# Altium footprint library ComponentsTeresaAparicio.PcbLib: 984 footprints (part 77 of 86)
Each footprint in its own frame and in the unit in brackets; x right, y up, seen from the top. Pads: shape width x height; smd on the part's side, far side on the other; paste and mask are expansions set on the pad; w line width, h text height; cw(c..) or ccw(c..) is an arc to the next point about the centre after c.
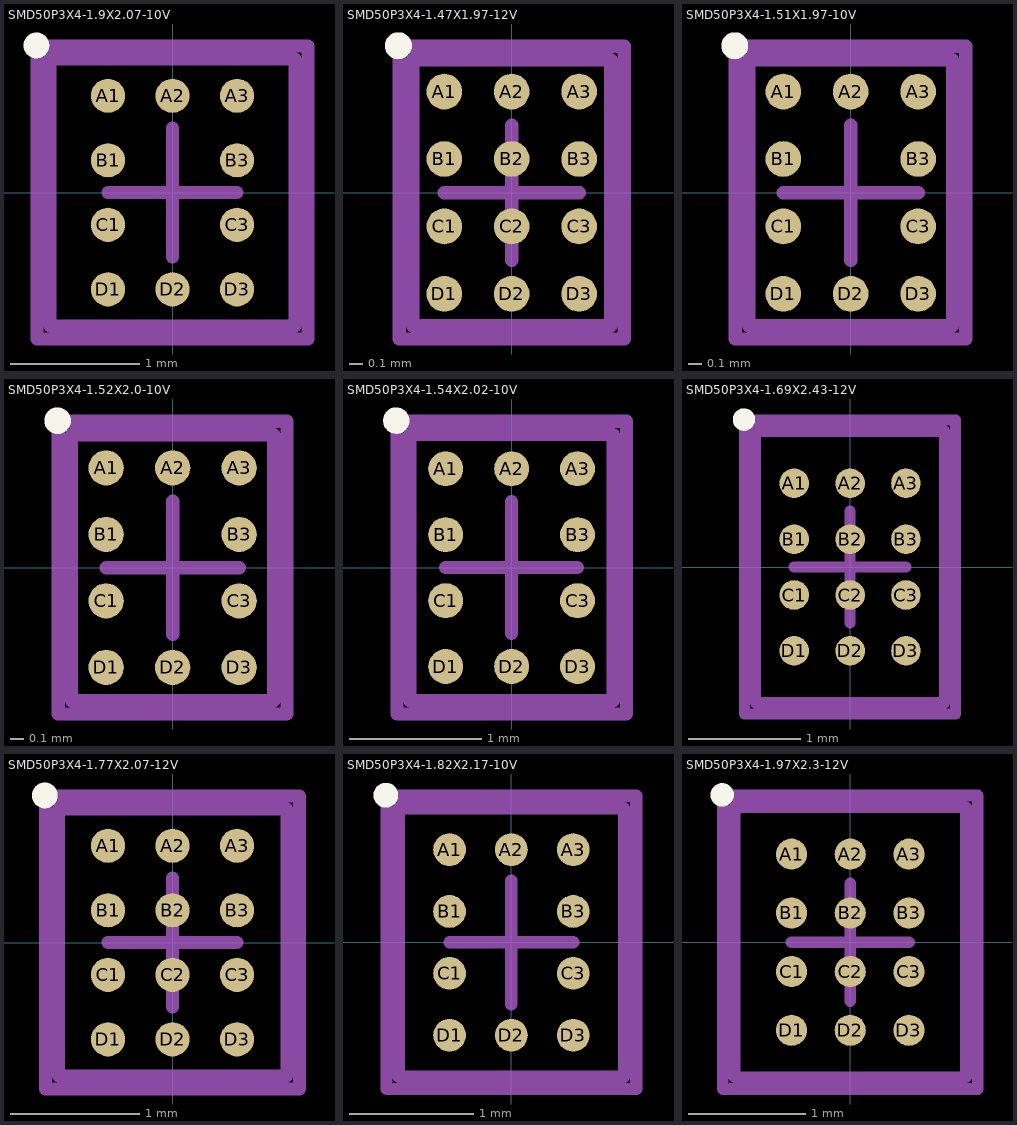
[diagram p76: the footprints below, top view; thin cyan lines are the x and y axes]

## SMD50P3X4-1.9X2.07-10V [mm] "Micro SMD, 10-Leads, Body 2.07x1.9mm, Pitch 0.5mm, NSC Recommended"
height 0.68
pads (10):
  round 0.265 smd paste-0.132 mask+0.05: A1(-0.5,0.75) A2(0,0.75) A3(0.5,0.75) B1(-0.5,0.25) B3(0.5,0.25) C1(-0.5,-0.25) C3(0.5,-0.25) D1(-0.5,-0.75) D2(0,-0.75) D3(0.5,-0.75)
Top Overlay:
  circle w0.1: c-1.055,1.14 r0.05
Top Paste:
  circle w0.05: c-0.6,0.7 r0.025
  circle w0.05: c-0.45,0.85 r0.025
  circle w0.05: c-0.45,0.7 r0.025
  circle w0.05: c-0.6,0.85 r0.025
  circle w0.05: c-0.075,0.7 r0.025
  circle w0.05: c0.075,0.85 r0.025
  circle w0.05: c0.075,0.7 r0.025
  circle w0.05: c-0.075,0.85 r0.025
  circle w0.05: c0.45,0.7 r0.025
  circle w0.05: c0.6,0.85 r0.025
  circle w0.05: c0.6,0.7 r0.025
  circle w0.05: c0.45,0.85 r0.025
  circle w0.05: c-0.6,0.175 r0.025
  circle w0.05: c-0.45,0.325 r0.025
  circle w0.05: c-0.45,0.175 r0.025
  circle w0.05: c-0.6,0.325 r0.025
  circle w0.05: c0.45,0.175 r0.025
  circle w0.05: c0.6,0.325 r0.025
  circle w0.05: c0.6,0.175 r0.025
  circle w0.05: c0.45,0.325 r0.025
  circle w0.05: c-0.6,-0.325 r0.025
  circle w0.05: c-0.45,-0.175 r0.025
  circle w0.05: c-0.45,-0.325 r0.025
  circle w0.05: c-0.6,-0.175 r0.025
  circle w0.05: c0.45,-0.325 r0.025
  circle w0.05: c0.6,-0.175 r0.025
  circle w0.05: c0.6,-0.325 r0.025
  circle w0.05: c0.45,-0.175 r0.025
  circle w0.05: c-0.6,-0.85 r0.025
  circle w0.05: c-0.45,-0.7 r0.025
  circle w0.05: c-0.45,-0.85 r0.025
  circle w0.05: c-0.6,-0.7 r0.025
  circle w0.05: c-0.075,-0.85 r0.025
  circle w0.05: c0.075,-0.7 r0.025
  circle w0.05: c0.075,-0.85 r0.025
  circle w0.05: c-0.075,-0.7 r0.025
  circle w0.05: c0.45,-0.85 r0.025
  circle w0.05: c0.6,-0.7 r0.025
  circle w0.05: c0.6,-0.85 r0.025
  circle w0.05: c0.45,-0.7 r0.025
  region: -0.6,0.85 -0.6,0.7 -0.45,0.7 -0.45,0.85
  region: -0.6,0.7 -0.6,0.85 -0.65,0.85 -0.65,0.7
  rectangle: -0.6,0.85 -0.45,0.9
  region: -0.45,0.85 -0.45,0.7 -0.4,0.7 -0.4,0.85
  region: -0.45,0.7 -0.6,0.7 -0.6,0.65 -0.45,0.65
  region: -0.075,0.85 -0.075,0.7 0.075,0.7 0.075,0.85
  region: -0.075,0.7 -0.075,0.85 -0.125,0.85 -0.125,0.7
  rectangle: -0.075,0.85 0.075,0.9
  region: 0.075,0.85 0.075,0.7 0.125,0.7 0.125,0.85
  region: 0.075,0.7 -0.075,0.7 -0.075,0.65 0.075,0.65
  region: 0.45,0.85 0.45,0.7 0.6,0.7 0.6,0.85
  region: 0.45,0.7 0.45,0.85 0.4,0.85 0.4,0.7
  rectangle: 0.45,0.85 0.6,0.9
  region: 0.6,0.85 0.6,0.7 0.65,0.7 0.65,0.85
  region: 0.6,0.7 0.45,0.7 0.45,0.65 0.6,0.65
  region: -0.6,0.325 -0.6,0.175 -0.45,0.175 -0.45,0.325
  region: -0.6,0.175 -0.6,0.325 -0.65,0.325 -0.65,0.175
  rectangle: -0.6,0.325 -0.45,0.375
  region: -0.45,0.325 -0.45,0.175 -0.4,0.175 -0.4,0.325
  region: -0.45,0.175 -0.6,0.175 -0.6,0.125 -0.45,0.125
  region: 0.45,0.325 0.45,0.175 0.6,0.175 0.6,0.325
  region: 0.45,0.175 0.45,0.325 0.4,0.325 0.4,0.175
  rectangle: 0.45,0.325 0.6,0.375
  region: 0.6,0.325 0.6,0.175 0.65,0.175 0.65,0.325
  region: 0.6,0.175 0.45,0.175 0.45,0.125 0.6,0.125
  region: -0.6,-0.175 -0.6,-0.325 -0.45,-0.325 -0.45,-0.175
  region: -0.6,-0.325 -0.6,-0.175 -0.65,-0.175 -0.65,-0.325
  rectangle: -0.6,-0.175 -0.45,-0.125
  region: -0.45,-0.175 -0.45,-0.325 -0.4,-0.325 -0.4,-0.175
  region: -0.45,-0.325 -0.6,-0.325 -0.6,-0.375 -0.45,-0.375
  region: 0.45,-0.175 0.45,-0.325 0.6,-0.325 0.6,-0.175
  region: 0.45,-0.325 0.45,-0.175 0.4,-0.175 0.4,-0.325
  rectangle: 0.45,-0.175 0.6,-0.125
  region: 0.6,-0.175 0.6,-0.325 0.65,-0.325 0.65,-0.175
  region: 0.6,-0.325 0.45,-0.325 0.45,-0.375 0.6,-0.375
  region: -0.6,-0.7 -0.6,-0.85 -0.45,-0.85 -0.45,-0.7
  region: -0.6,-0.85 -0.6,-0.7 -0.65,-0.7 -0.65,-0.85
  rectangle: -0.6,-0.7 -0.45,-0.65
  region: -0.45,-0.7 -0.45,-0.85 -0.4,-0.85 -0.4,-0.7
  region: -0.45,-0.85 -0.6,-0.85 -0.6,-0.9 -0.45,-0.9
  region: -0.075,-0.7 -0.075,-0.85 0.075,-0.85 0.075,-0.7
  region: -0.075,-0.85 -0.075,-0.7 -0.125,-0.7 -0.125,-0.85
  rectangle: -0.075,-0.7 0.075,-0.65
  region: 0.075,-0.7 0.075,-0.85 0.125,-0.85 0.125,-0.7
  region: 0.075,-0.85 -0.075,-0.85 -0.075,-0.9 0.075,-0.9
  region: 0.45,-0.7 0.45,-0.85 0.6,-0.85 0.6,-0.7
  region: 0.45,-0.85 0.45,-0.7 0.4,-0.7 0.4,-0.85
  rectangle: 0.45,-0.7 0.6,-0.65
  region: 0.6,-0.7 0.6,-0.85 0.65,-0.85 0.65,-0.7
  region: 0.6,-0.85 0.45,-0.85 0.45,-0.9 0.6,-0.9
Mechanical 13:
  lines w0.1: -0.95,-1.035 -0.95,1.035 0.95,1.035 0.95,-1.035 -0.95,-1.035
Mechanical 15:
  lines w0.1: -0.5,0 0.5,0 ; 0,-0.5 0,0.5 ; -1.05,-1.135 -1.05,1.135 1.05,1.135 1.05,-1.135 -1.05,-1.135
3D body: height 0.68, standoff 0, extent -0.95,-1.04 0.95,1.04

## SMD50P3X4-1.47X1.97-12V [mm] "Micro SMD, 12-Leads, Body 1.97x1.47mm, Pitch 0.5mm, NSC Recommended"
height 0.68
pads (12):
  round 0.265 smd paste-0.132 mask+0.05: A1(-0.5,0.75) A2(0,0.75) A3(0.5,0.75) B1(-0.5,0.25) B2(0,0.25) B3(0.5,0.25) C1(-0.5,-0.25) C2(0,-0.25) C3(0.5,-0.25) D1(-0.5,-0.75) D2(0,-0.75) D3(0.5,-0.75)
Top Overlay:
  circle w0.1: c-0.84,1.09 r0.05
Top Paste:
  circle w0.05: c-0.6,0.7 r0.025
  circle w0.05: c-0.45,0.85 r0.025
  circle w0.05: c-0.6,0.85 r0.025
  circle w0.05: c-0.45,0.7 r0.025
  circle w0.05: c0.45,0.85 r0.025
  circle w0.05: c0.6,0.7 r0.025
  circle w0.05: c0.6,0.85 r0.025
  circle w0.05: c0.45,0.7 r0.025
  circle w0.05: c0.6,-0.7 r0.025
  circle w0.05: c0.45,-0.85 r0.025
  circle w0.05: c0.6,-0.85 r0.025
  circle w0.05: c0.45,-0.7 r0.025
  circle w0.05: c-0.45,-0.85 r0.025
  circle w0.05: c-0.6,-0.7 r0.025
  circle w0.05: c-0.6,-0.85 r0.025
  circle w0.05: c-0.45,-0.7 r0.025
  circle w0.05: c-0.075,0.7 r0.025
  circle w0.05: c0.075,0.85 r0.025
  circle w0.05: c0.075,0.7 r0.025
  circle w0.05: c-0.075,0.85 r0.025
  circle w0.05: c-0.45,0.175 r0.025
  circle w0.05: c-0.6,0.325 r0.025
  circle w0.05: c-0.45,0.325 r0.025
  circle w0.05: c-0.6,0.175 r0.025
  circle w0.05: c-0.45,-0.325 r0.025
  circle w0.05: c-0.6,-0.175 r0.025
  circle w0.05: c-0.45,-0.175 r0.025
  circle w0.05: c-0.6,-0.325 r0.025
  circle w0.05: c0.075,-0.7 r0.025
  circle w0.05: c-0.075,-0.85 r0.025
  circle w0.05: c-0.075,-0.7 r0.025
  circle w0.05: c0.075,-0.85 r0.025
  circle w0.05: c0.45,-0.175 r0.025
  circle w0.05: c0.6,-0.325 r0.025
  circle w0.05: c0.45,-0.325 r0.025
  circle w0.05: c0.6,-0.175 r0.025
  circle w0.05: c0.45,0.325 r0.025
  circle w0.05: c0.6,0.175 r0.025
  circle w0.05: c0.45,0.175 r0.025
  circle w0.05: c0.6,0.325 r0.025
  circle w0.05: c0.075,0.175 r0.025
  circle w0.05: c-0.075,0.325 r0.025
  circle w0.05: c-0.075,0.175 r0.025
  circle w0.05: c0.075,0.325 r0.025
  circle w0.05: c0.075,-0.325 r0.025
  circle w0.05: c-0.075,-0.175 r0.025
  circle w0.05: c-0.075,-0.325 r0.025
  circle w0.05: c0.075,-0.175 r0.025
  region: -0.45,0.85 -0.45,0.7 -0.4,0.7 -0.4,0.85
  rectangle: -0.6,0.85 -0.45,0.9
  region: -0.6,0.7 -0.6,0.85 -0.65,0.85 -0.65,0.7
  region: -0.45,0.7 -0.6,0.7 -0.6,0.65 -0.45,0.65
  rectangle: -0.6,0.7 -0.45,0.85
  region: 0.6,0.7 0.45,0.7 0.45,0.65 0.6,0.65
  region: 0.6,0.85 0.6,0.7 0.65,0.7 0.65,0.85
  rectangle: 0.45,0.85 0.6,0.9
  region: 0.45,0.7 0.45,0.85 0.4,0.85 0.4,0.7
  region: 0.45,0.85 0.45,0.7 0.6,0.7 0.6,0.85
  region: 0.45,-0.85 0.45,-0.7 0.4,-0.7 0.4,-0.85
  region: 0.6,-0.85 0.45,-0.85 0.45,-0.9 0.6,-0.9
  region: 0.6,-0.7 0.6,-0.85 0.65,-0.85 0.65,-0.7
  rectangle: 0.45,-0.7 0.6,-0.65
  region: 0.6,-0.7 0.45,-0.7 0.45,-0.85 0.6,-0.85
  rectangle: -0.6,-0.7 -0.45,-0.65
  region: -0.6,-0.85 -0.6,-0.7 -0.65,-0.7 -0.65,-0.85
  region: -0.45,-0.85 -0.6,-0.85 -0.6,-0.9 -0.45,-0.9
  region: -0.45,-0.7 -0.45,-0.85 -0.4,-0.85 -0.4,-0.7
  region: -0.45,-0.85 -0.45,-0.7 -0.6,-0.7 -0.6,-0.85
  region: -0.075,0.85 -0.075,0.7 0.075,0.7 0.075,0.85
  region: -0.075,0.7 -0.075,0.85 -0.125,0.85 -0.125,0.7
  rectangle: -0.075,0.85 0.075,0.9
  region: 0.075,0.85 0.075,0.7 0.125,0.7 0.125,0.85
  region: 0.075,0.7 -0.075,0.7 -0.075,0.65 0.075,0.65
  rectangle: -0.6,0.175 -0.45,0.325
  region: -0.45,0.175 -0.6,0.175 -0.6,0.125 -0.45,0.125
  region: -0.6,0.175 -0.6,0.325 -0.65,0.325 -0.65,0.175
  rectangle: -0.6,0.325 -0.45,0.375
  region: -0.45,0.325 -0.45,0.175 -0.4,0.175 -0.4,0.325
  rectangle: -0.6,-0.325 -0.45,-0.175
  region: -0.45,-0.325 -0.6,-0.325 -0.6,-0.375 -0.45,-0.375
  region: -0.6,-0.325 -0.6,-0.175 -0.65,-0.175 -0.65,-0.325
  rectangle: -0.6,-0.175 -0.45,-0.125
  region: -0.45,-0.175 -0.45,-0.325 -0.4,-0.325 -0.4,-0.175
  region: 0.075,-0.85 0.075,-0.7 -0.075,-0.7 -0.075,-0.85
  region: 0.075,-0.7 0.075,-0.85 0.125,-0.85 0.125,-0.7
  region: 0.075,-0.85 -0.075,-0.85 -0.075,-0.9 0.075,-0.9
  region: -0.075,-0.85 -0.075,-0.7 -0.125,-0.7 -0.125,-0.85
  rectangle: -0.075,-0.7 0.075,-0.65
  region: 0.6,-0.175 0.45,-0.175 0.45,-0.325 0.6,-0.325
  rectangle: 0.45,-0.175 0.6,-0.125
  region: 0.6,-0.175 0.6,-0.325 0.65,-0.325 0.65,-0.175
  region: 0.6,-0.325 0.45,-0.325 0.45,-0.375 0.6,-0.375
  region: 0.45,-0.325 0.45,-0.175 0.4,-0.175 0.4,-0.325
  region: 0.6,0.325 0.45,0.325 0.45,0.175 0.6,0.175
  rectangle: 0.45,0.325 0.6,0.375
  region: 0.6,0.325 0.6,0.175 0.65,0.175 0.65,0.325
  region: 0.6,0.175 0.45,0.175 0.45,0.125 0.6,0.125
  region: 0.45,0.175 0.45,0.325 0.4,0.325 0.4,0.175
  region: -0.075,0.325 -0.075,0.175 0.075,0.175 0.075,0.325
  region: 0.125,0.175 0.125,0.325 0.075,0.325 0.075,0.175
  region: 0.075,0.375 -0.075,0.375 -0.075,0.325 0.075,0.325
  region: -0.125,0.325 -0.125,0.175 -0.075,0.175 -0.075,0.325
  rectangle: -0.075,0.125 0.075,0.175
  region: -0.075,-0.175 -0.075,-0.325 0.075,-0.325 0.075,-0.175
  region: 0.125,-0.325 0.125,-0.175 0.075,-0.175 0.075,-0.325
  region: 0.075,-0.125 -0.075,-0.125 -0.075,-0.175 0.075,-0.175
  region: -0.125,-0.175 -0.125,-0.325 -0.075,-0.325 -0.075,-0.175
  rectangle: -0.075,-0.375 0.075,-0.325
Mechanical 13:
  lines w0.1: -0.735,-0.985 0.735,-0.985 0.735,0.985 -0.735,0.985 -0.735,-0.985
Mechanical 15:
  lines w0.1: -0.5,0 0.5,0 ; 0,-0.5 0,0.5 ; -0.835,-1.085 0.835,-1.085 0.835,1.085 -0.835,1.085 -0.835,-1.085
3D body: height 0.68, standoff 0, extent -0.734,-0.984 0.734,0.984

## SMD50P3X4-1.51X1.97-10V [mm] "Micro SMD, 10-Leads, Body 1.97x1.51mm, Pitch 0.5mm, NSC Recommended"
height 0.68
pads (10):
  round 0.265 smd paste-0.132 mask+0.05: A1(-0.5,0.75) A2(0,0.75) A3(0.5,0.75) B1(-0.5,0.25) B3(0.5,0.25) C1(-0.5,-0.25) C3(0.5,-0.25) D1(-0.5,-0.75) D2(0,-0.75) D3(0.5,-0.75)
Top Overlay:
  circle w0.1: c-0.86,1.09 r0.05
Top Paste:
  circle w0.05: c0.45,-0.7 r0.025
  circle w0.05: c0.6,-0.85 r0.025
  circle w0.05: c0.6,-0.7 r0.025
  circle w0.05: c0.45,-0.85 r0.025
  circle w0.05: c-0.075,-0.7 r0.025
  circle w0.05: c0.075,-0.85 r0.025
  circle w0.05: c0.075,-0.7 r0.025
  circle w0.05: c-0.075,-0.85 r0.025
  circle w0.05: c-0.6,-0.7 r0.025
  circle w0.05: c-0.45,-0.85 r0.025
  circle w0.05: c-0.45,-0.7 r0.025
  circle w0.05: c-0.6,-0.85 r0.025
  circle w0.05: c0.45,-0.175 r0.025
  circle w0.05: c0.6,-0.325 r0.025
  circle w0.05: c0.6,-0.175 r0.025
  circle w0.05: c0.45,-0.325 r0.025
  circle w0.05: c-0.6,-0.175 r0.025
  circle w0.05: c-0.45,-0.325 r0.025
  circle w0.05: c-0.45,-0.175 r0.025
  circle w0.05: c-0.6,-0.325 r0.025
  circle w0.05: c0.45,0.325 r0.025
  circle w0.05: c0.6,0.175 r0.025
  circle w0.05: c0.6,0.325 r0.025
  circle w0.05: c0.45,0.175 r0.025
  circle w0.05: c-0.6,0.325 r0.025
  circle w0.05: c-0.45,0.175 r0.025
  circle w0.05: c-0.45,0.325 r0.025
  circle w0.05: c-0.6,0.175 r0.025
  circle w0.05: c0.45,0.85 r0.025
  circle w0.05: c0.6,0.7 r0.025
  circle w0.05: c0.6,0.85 r0.025
  circle w0.05: c0.45,0.7 r0.025
  circle w0.05: c-0.075,0.85 r0.025
  circle w0.05: c0.075,0.7 r0.025
  circle w0.05: c0.075,0.85 r0.025
  circle w0.05: c-0.075,0.7 r0.025
  circle w0.05: c-0.6,0.85 r0.025
  circle w0.05: c-0.45,0.7 r0.025
  circle w0.05: c-0.45,0.85 r0.025
  circle w0.05: c-0.6,0.7 r0.025
  region: 0.6,-0.85 0.45,-0.85 0.45,-0.9 0.6,-0.9
  region: 0.6,-0.7 0.6,-0.85 0.65,-0.85 0.65,-0.7
  rectangle: 0.45,-0.7 0.6,-0.65
  region: 0.45,-0.85 0.45,-0.7 0.4,-0.7 0.4,-0.85
  region: 0.45,-0.7 0.45,-0.85 0.6,-0.85 0.6,-0.7
  region: 0.075,-0.85 -0.075,-0.85 -0.075,-0.9 0.075,-0.9
  region: 0.075,-0.7 0.075,-0.85 0.125,-0.85 0.125,-0.7
  rectangle: -0.075,-0.7 0.075,-0.65
  region: -0.075,-0.85 -0.075,-0.7 -0.125,-0.7 -0.125,-0.85
  region: -0.075,-0.7 -0.075,-0.85 0.075,-0.85 0.075,-0.7
  region: -0.45,-0.85 -0.6,-0.85 -0.6,-0.9 -0.45,-0.9
  region: -0.45,-0.7 -0.45,-0.85 -0.4,-0.85 -0.4,-0.7
  rectangle: -0.6,-0.7 -0.45,-0.65
  region: -0.6,-0.85 -0.6,-0.7 -0.65,-0.7 -0.65,-0.85
  region: -0.6,-0.7 -0.6,-0.85 -0.45,-0.85 -0.45,-0.7
  region: 0.6,-0.325 0.45,-0.325 0.45,-0.375 0.6,-0.375
  region: 0.6,-0.175 0.6,-0.325 0.65,-0.325 0.65,-0.175
  rectangle: 0.45,-0.175 0.6,-0.125
  region: 0.45,-0.325 0.45,-0.175 0.4,-0.175 0.4,-0.325
  region: 0.45,-0.175 0.45,-0.325 0.6,-0.325 0.6,-0.175
  region: -0.45,-0.325 -0.6,-0.325 -0.6,-0.375 -0.45,-0.375
  region: -0.45,-0.175 -0.45,-0.325 -0.4,-0.325 -0.4,-0.175
  rectangle: -0.6,-0.175 -0.45,-0.125
  region: -0.6,-0.325 -0.6,-0.175 -0.65,-0.175 -0.65,-0.325
  region: -0.6,-0.175 -0.6,-0.325 -0.45,-0.325 -0.45,-0.175
  region: 0.6,0.175 0.45,0.175 0.45,0.125 0.6,0.125
  region: 0.6,0.325 0.6,0.175 0.65,0.175 0.65,0.325
  rectangle: 0.45,0.325 0.6,0.375
  region: 0.45,0.175 0.45,0.325 0.4,0.325 0.4,0.175
  region: 0.45,0.325 0.45,0.175 0.6,0.175 0.6,0.325
  region: -0.45,0.175 -0.6,0.175 -0.6,0.125 -0.45,0.125
  region: -0.45,0.325 -0.45,0.175 -0.4,0.175 -0.4,0.325
  rectangle: -0.6,0.325 -0.45,0.375
  region: -0.6,0.175 -0.6,0.325 -0.65,0.325 -0.65,0.175
  region: -0.6,0.325 -0.6,0.175 -0.45,0.175 -0.45,0.325
  region: 0.6,0.7 0.45,0.7 0.45,0.65 0.6,0.65
  region: 0.6,0.85 0.6,0.7 0.65,0.7 0.65,0.85
  rectangle: 0.45,0.85 0.6,0.9
  region: 0.45,0.7 0.45,0.85 0.4,0.85 0.4,0.7
  region: 0.45,0.85 0.45,0.7 0.6,0.7 0.6,0.85
  region: 0.075,0.7 -0.075,0.7 -0.075,0.65 0.075,0.65
  region: 0.075,0.85 0.075,0.7 0.125,0.7 0.125,0.85
  rectangle: -0.075,0.85 0.075,0.9
  region: -0.075,0.7 -0.075,0.85 -0.125,0.85 -0.125,0.7
  region: -0.075,0.85 -0.075,0.7 0.075,0.7 0.075,0.85
  region: -0.45,0.7 -0.6,0.7 -0.6,0.65 -0.45,0.65
  region: -0.45,0.85 -0.45,0.7 -0.4,0.7 -0.4,0.85
  rectangle: -0.6,0.85 -0.45,0.9
  region: -0.6,0.7 -0.6,0.85 -0.65,0.85 -0.65,0.7
  region: -0.6,0.85 -0.6,0.7 -0.45,0.7 -0.45,0.85
Mechanical 13:
  lines w0.1: -0.755,-0.985 0.755,-0.985 0.755,0.985 -0.755,0.985 -0.755,-0.985
Mechanical 15:
  lines w0.1: -0.5,0 0.5,0 ; 0,-0.5 0,0.5 ; -0.855,-1.085 0.855,-1.085 0.855,1.085 -0.855,1.085 -0.855,-1.085
3D body: height 0.68, standoff 0, extent -0.76,-0.985 0.76,0.985

## SMD50P3X4-1.52X2.0-10V [mm] "Micro SMD, 10-Leads, Body 2.0x1.52mm, Pitch 0.5mm, NSC Recommended"
height 1.05
pads (10):
  round 0.265 smd paste-0.132 mask+0.05: A1(-0.5,0.75) A2(0,0.75) A3(0.5,0.75) B1(-0.5,0.25) B3(0.5,0.25) C1(-0.5,-0.25) C3(0.5,-0.25) D1(-0.5,-0.75) D2(0,-0.75) D3(0.5,-0.75)
Top Overlay:
  circle w0.1: c-0.865,1.105 r0.05
Top Paste:
  circle w0.05: c-0.6,0.7 r0.025
  circle w0.05: c-0.45,0.85 r0.025
  circle w0.05: c-0.6,0.85 r0.025
  circle w0.05: c-0.45,0.7 r0.025
  circle w0.05: c0.45,0.85 r0.025
  circle w0.05: c0.6,0.7 r0.025
  circle w0.05: c0.6,0.85 r0.025
  circle w0.05: c0.45,0.7 r0.025
  circle w0.05: c0.6,-0.7 r0.025
  circle w0.05: c0.45,-0.85 r0.025
  circle w0.05: c0.6,-0.85 r0.025
  circle w0.05: c0.45,-0.7 r0.025
  circle w0.05: c-0.45,-0.85 r0.025
  circle w0.05: c-0.6,-0.7 r0.025
  circle w0.05: c-0.6,-0.85 r0.025
  circle w0.05: c-0.45,-0.7 r0.025
  circle w0.05: c-0.075,0.7 r0.025
  circle w0.05: c0.075,0.85 r0.025
  circle w0.05: c0.075,0.7 r0.025
  circle w0.05: c-0.075,0.85 r0.025
  circle w0.05: c-0.45,0.175 r0.025
  circle w0.05: c-0.6,0.325 r0.025
  circle w0.05: c-0.45,0.325 r0.025
  circle w0.05: c-0.6,0.175 r0.025
  circle w0.05: c-0.45,-0.325 r0.025
  circle w0.05: c-0.6,-0.175 r0.025
  circle w0.05: c-0.45,-0.175 r0.025
  circle w0.05: c-0.6,-0.325 r0.025
  circle w0.05: c0.075,-0.7 r0.025
  circle w0.05: c-0.075,-0.85 r0.025
  circle w0.05: c-0.075,-0.7 r0.025
  circle w0.05: c0.075,-0.85 r0.025
  circle w0.05: c0.45,-0.175 r0.025
  circle w0.05: c0.6,-0.325 r0.025
  circle w0.05: c0.45,-0.325 r0.025
  circle w0.05: c0.6,-0.175 r0.025
  circle w0.05: c0.45,0.325 r0.025
  circle w0.05: c0.6,0.175 r0.025
  circle w0.05: c0.45,0.175 r0.025
  circle w0.05: c0.6,0.325 r0.025
  region: -0.45,0.85 -0.45,0.7 -0.4,0.7 -0.4,0.85
  rectangle: -0.6,0.85 -0.45,0.9
  region: -0.6,0.7 -0.6,0.85 -0.65,0.85 -0.65,0.7
  region: -0.45,0.7 -0.6,0.7 -0.6,0.65 -0.45,0.65
  rectangle: -0.6,0.7 -0.45,0.85
  region: 0.6,0.7 0.45,0.7 0.45,0.65 0.6,0.65
  region: 0.6,0.85 0.6,0.7 0.65,0.7 0.65,0.85
  rectangle: 0.45,0.85 0.6,0.9
  region: 0.45,0.7 0.45,0.85 0.4,0.85 0.4,0.7
  region: 0.45,0.85 0.45,0.7 0.6,0.7 0.6,0.85
  region: 0.45,-0.85 0.45,-0.7 0.4,-0.7 0.4,-0.85
  region: 0.6,-0.85 0.45,-0.85 0.45,-0.9 0.6,-0.9
  region: 0.6,-0.7 0.6,-0.85 0.65,-0.85 0.65,-0.7
  rectangle: 0.45,-0.7 0.6,-0.65
  region: 0.6,-0.7 0.45,-0.7 0.45,-0.85 0.6,-0.85
  rectangle: -0.6,-0.7 -0.45,-0.65
  region: -0.6,-0.85 -0.6,-0.7 -0.65,-0.7 -0.65,-0.85
  region: -0.45,-0.85 -0.6,-0.85 -0.6,-0.9 -0.45,-0.9
  region: -0.45,-0.7 -0.45,-0.85 -0.4,-0.85 -0.4,-0.7
  region: -0.45,-0.85 -0.45,-0.7 -0.6,-0.7 -0.6,-0.85
  region: -0.075,0.85 -0.075,0.7 0.075,0.7 0.075,0.85
  region: -0.075,0.7 -0.075,0.85 -0.125,0.85 -0.125,0.7
  rectangle: -0.075,0.85 0.075,0.9
  region: 0.075,0.85 0.075,0.7 0.125,0.7 0.125,0.85
  region: 0.075,0.7 -0.075,0.7 -0.075,0.65 0.075,0.65
  rectangle: -0.6,0.175 -0.45,0.325
  region: -0.45,0.175 -0.6,0.175 -0.6,0.125 -0.45,0.125
  region: -0.6,0.175 -0.6,0.325 -0.65,0.325 -0.65,0.175
  rectangle: -0.6,0.325 -0.45,0.375
  region: -0.45,0.325 -0.45,0.175 -0.4,0.175 -0.4,0.325
  rectangle: -0.6,-0.325 -0.45,-0.175
  region: -0.45,-0.325 -0.6,-0.325 -0.6,-0.375 -0.45,-0.375
  region: -0.6,-0.325 -0.6,-0.175 -0.65,-0.175 -0.65,-0.325
  rectangle: -0.6,-0.175 -0.45,-0.125
  region: -0.45,-0.175 -0.45,-0.325 -0.4,-0.325 -0.4,-0.175
  region: 0.075,-0.85 0.075,-0.7 -0.075,-0.7 -0.075,-0.85
  region: 0.075,-0.7 0.075,-0.85 0.125,-0.85 0.125,-0.7
  region: 0.075,-0.85 -0.075,-0.85 -0.075,-0.9 0.075,-0.9
  region: -0.075,-0.85 -0.075,-0.7 -0.125,-0.7 -0.125,-0.85
  rectangle: -0.075,-0.7 0.075,-0.65
  region: 0.6,-0.175 0.45,-0.175 0.45,-0.325 0.6,-0.325
  rectangle: 0.45,-0.175 0.6,-0.125
  region: 0.6,-0.175 0.6,-0.325 0.65,-0.325 0.65,-0.175
  region: 0.6,-0.325 0.45,-0.325 0.45,-0.375 0.6,-0.375
  region: 0.45,-0.325 0.45,-0.175 0.4,-0.175 0.4,-0.325
  region: 0.6,0.325 0.45,0.325 0.45,0.175 0.6,0.175
  rectangle: 0.45,0.325 0.6,0.375
  region: 0.6,0.325 0.6,0.175 0.65,0.175 0.65,0.325
  region: 0.6,0.175 0.45,0.175 0.45,0.125 0.6,0.125
  region: 0.45,0.175 0.45,0.325 0.4,0.325 0.4,0.175
Mechanical 13:
  lines w0.1: -0.76,-1 -0.76,1 0.76,1 0.76,-1 -0.76,-1
Mechanical 15:
  lines w0.1: -0.5,0 0.5,0 ; 0,-0.5 0,0.5 ; -0.86,-1.1 -0.86,1.1 0.86,1.1 0.86,-1.1 -0.86,-1.1
3D body: height 1.05, standoff 0, extent -0.759,-0.999 0.759,0.999

## SMD50P3X4-1.54X2.02-10V [mm] "Micro SMD, 10-Leads, Body 2.02x1.54mm, Pitch 0.5mm, NSC Recommended"
height 0.68
pads (10):
  round 0.265 smd paste-0.132 mask+0.05: A1(-0.5,0.75) A2(0,0.75) A3(0.5,0.75) B1(-0.5,0.25) B3(0.5,0.25) C1(-0.5,-0.25) C3(0.5,-0.25) D1(-0.5,-0.75) D2(0,-0.75) D3(0.5,-0.75)
Top Overlay:
  circle w0.1: c-0.875,1.115 r0.05
Top Paste:
  circle w0.05: c-0.6,0.7 r0.025
  circle w0.05: c-0.45,0.85 r0.025
  circle w0.05: c-0.6,0.85 r0.025
  circle w0.05: c-0.45,0.7 r0.025
  circle w0.05: c0.45,0.85 r0.025
  circle w0.05: c0.6,0.7 r0.025
  circle w0.05: c0.6,0.85 r0.025
  circle w0.05: c0.45,0.7 r0.025
  circle w0.05: c0.6,-0.7 r0.025
  circle w0.05: c0.45,-0.85 r0.025
  circle w0.05: c0.6,-0.85 r0.025
  circle w0.05: c0.45,-0.7 r0.025
  circle w0.05: c-0.45,-0.85 r0.025
  circle w0.05: c-0.6,-0.7 r0.025
  circle w0.05: c-0.6,-0.85 r0.025
  circle w0.05: c-0.45,-0.7 r0.025
  circle w0.05: c-0.075,0.7 r0.025
  circle w0.05: c0.075,0.85 r0.025
  circle w0.05: c0.075,0.7 r0.025
  circle w0.05: c-0.075,0.85 r0.025
  circle w0.05: c-0.45,0.175 r0.025
  circle w0.05: c-0.6,0.325 r0.025
  circle w0.05: c-0.45,0.325 r0.025
  circle w0.05: c-0.6,0.175 r0.025
  circle w0.05: c-0.45,-0.325 r0.025
  circle w0.05: c-0.6,-0.175 r0.025
  circle w0.05: c-0.45,-0.175 r0.025
  circle w0.05: c-0.6,-0.325 r0.025
  circle w0.05: c0.075,-0.7 r0.025
  circle w0.05: c-0.075,-0.85 r0.025
  circle w0.05: c-0.075,-0.7 r0.025
  circle w0.05: c0.075,-0.85 r0.025
  circle w0.05: c0.45,-0.175 r0.025
  circle w0.05: c0.6,-0.325 r0.025
  circle w0.05: c0.45,-0.325 r0.025
  circle w0.05: c0.6,-0.175 r0.025
  circle w0.05: c0.45,0.325 r0.025
  circle w0.05: c0.6,0.175 r0.025
  circle w0.05: c0.45,0.175 r0.025
  circle w0.05: c0.6,0.325 r0.025
  region: -0.45,0.85 -0.45,0.7 -0.4,0.7 -0.4,0.85
  rectangle: -0.6,0.85 -0.45,0.9
  region: -0.6,0.7 -0.6,0.85 -0.65,0.85 -0.65,0.7
  region: -0.45,0.7 -0.6,0.7 -0.6,0.65 -0.45,0.65
  rectangle: -0.6,0.7 -0.45,0.85
  region: 0.6,0.7 0.45,0.7 0.45,0.65 0.6,0.65
  region: 0.6,0.85 0.6,0.7 0.65,0.7 0.65,0.85
  rectangle: 0.45,0.85 0.6,0.9
  region: 0.45,0.7 0.45,0.85 0.4,0.85 0.4,0.7
  region: 0.45,0.85 0.45,0.7 0.6,0.7 0.6,0.85
  region: 0.45,-0.85 0.45,-0.7 0.4,-0.7 0.4,-0.85
  region: 0.6,-0.85 0.45,-0.85 0.45,-0.9 0.6,-0.9
  region: 0.6,-0.7 0.6,-0.85 0.65,-0.85 0.65,-0.7
  rectangle: 0.45,-0.7 0.6,-0.65
  region: 0.6,-0.7 0.45,-0.7 0.45,-0.85 0.6,-0.85
  rectangle: -0.6,-0.7 -0.45,-0.65
  region: -0.6,-0.85 -0.6,-0.7 -0.65,-0.7 -0.65,-0.85
  region: -0.45,-0.85 -0.6,-0.85 -0.6,-0.9 -0.45,-0.9
  region: -0.45,-0.7 -0.45,-0.85 -0.4,-0.85 -0.4,-0.7
  region: -0.45,-0.85 -0.45,-0.7 -0.6,-0.7 -0.6,-0.85
  region: -0.075,0.85 -0.075,0.7 0.075,0.7 0.075,0.85
  region: -0.075,0.7 -0.075,0.85 -0.125,0.85 -0.125,0.7
  rectangle: -0.075,0.85 0.075,0.9
  region: 0.075,0.85 0.075,0.7 0.125,0.7 0.125,0.85
  region: 0.075,0.7 -0.075,0.7 -0.075,0.65 0.075,0.65
  rectangle: -0.6,0.175 -0.45,0.325
  region: -0.45,0.175 -0.6,0.175 -0.6,0.125 -0.45,0.125
  region: -0.6,0.175 -0.6,0.325 -0.65,0.325 -0.65,0.175
  rectangle: -0.6,0.325 -0.45,0.375
  region: -0.45,0.325 -0.45,0.175 -0.4,0.175 -0.4,0.325
  rectangle: -0.6,-0.325 -0.45,-0.175
  region: -0.45,-0.325 -0.6,-0.325 -0.6,-0.375 -0.45,-0.375
  region: -0.6,-0.325 -0.6,-0.175 -0.65,-0.175 -0.65,-0.325
  rectangle: -0.6,-0.175 -0.45,-0.125
  region: -0.45,-0.175 -0.45,-0.325 -0.4,-0.325 -0.4,-0.175
  region: 0.075,-0.85 0.075,-0.7 -0.075,-0.7 -0.075,-0.85
  region: 0.075,-0.7 0.075,-0.85 0.125,-0.85 0.125,-0.7
  region: 0.075,-0.85 -0.075,-0.85 -0.075,-0.9 0.075,-0.9
  region: -0.075,-0.85 -0.075,-0.7 -0.125,-0.7 -0.125,-0.85
  rectangle: -0.075,-0.7 0.075,-0.65
  region: 0.6,-0.175 0.45,-0.175 0.45,-0.325 0.6,-0.325
  rectangle: 0.45,-0.175 0.6,-0.125
  region: 0.6,-0.175 0.6,-0.325 0.65,-0.325 0.65,-0.175
  region: 0.6,-0.325 0.45,-0.325 0.45,-0.375 0.6,-0.375
  region: 0.45,-0.325 0.45,-0.175 0.4,-0.175 0.4,-0.325
  region: 0.6,0.325 0.45,0.325 0.45,0.175 0.6,0.175
  rectangle: 0.45,0.325 0.6,0.375
  region: 0.6,0.325 0.6,0.175 0.65,0.175 0.65,0.325
  region: 0.6,0.175 0.45,0.175 0.45,0.125 0.6,0.125
  region: 0.45,0.175 0.45,0.325 0.4,0.325 0.4,0.175
Mechanical 13:
  lines w0.1: -0.77,-1.01 -0.77,1.01 0.77,1.01 0.77,-1.01 -0.77,-1.01
Mechanical 15:
  lines w0.1: -0.5,0 0.5,0 ; 0,-0.5 0,0.5 ; -0.87,-1.11 -0.87,1.11 0.87,1.11 0.87,-1.11 -0.87,-1.11
3D body: height 0.68, standoff 0, extent -0.769,-1.009 0.769,1.009

## SMD50P3X4-1.69X2.43-12V [mm] "Micro SMD, 12-Leads, Body 2.43x1.69mm, Pitch 0.5mm, NSC Recommended"
height 0.68
pads (12):
  round 0.265 smd paste-0.132 mask+0.05: A1(-0.5,0.75) A2(0,0.75) A3(0.5,0.75) B1(-0.5,0.25) B2(0,0.25) B3(0.5,0.25) C1(-0.5,-0.25) C2(0,-0.25) C3(0.5,-0.25) D1(-0.5,-0.75) D2(0,-0.75) D3(0.5,-0.75)
Top Overlay:
  circle w0.1: c-0.95,1.32 r0.05
Top Paste:
  circle w0.05: c-0.6,0.7 r0.025
  circle w0.05: c-0.45,0.85 r0.025
  circle w0.05: c-0.45,0.7 r0.025
  circle w0.05: c-0.6,0.85 r0.025
  circle w0.05: c-0.075,0.7 r0.025
  circle w0.05: c0.075,0.85 r0.025
  circle w0.05: c0.075,0.7 r0.025
  circle w0.05: c-0.075,0.85 r0.025
  circle w0.05: c0.45,0.7 r0.025
  circle w0.05: c0.6,0.85 r0.025
  circle w0.05: c0.6,0.7 r0.025
  circle w0.05: c0.45,0.85 r0.025
  circle w0.05: c-0.6,0.175 r0.025
  circle w0.05: c-0.45,0.325 r0.025
  circle w0.05: c-0.45,0.175 r0.025
  circle w0.05: c-0.6,0.325 r0.025
  circle w0.05: c-0.075,0.175 r0.025
  circle w0.05: c0.075,0.325 r0.025
  circle w0.05: c0.075,0.175 r0.025
  circle w0.05: c-0.075,0.325 r0.025
  circle w0.05: c0.45,0.175 r0.025
  circle w0.05: c0.6,0.325 r0.025
  circle w0.05: c0.6,0.175 r0.025
  circle w0.05: c0.45,0.325 r0.025
  circle w0.05: c-0.6,-0.325 r0.025
  circle w0.05: c-0.45,-0.175 r0.025
  circle w0.05: c-0.45,-0.325 r0.025
  circle w0.05: c-0.6,-0.175 r0.025
  circle w0.05: c-0.075,-0.325 r0.025
  circle w0.05: c0.075,-0.175 r0.025
  circle w0.05: c0.075,-0.325 r0.025
  circle w0.05: c-0.075,-0.175 r0.025
  circle w0.05: c0.45,-0.325 r0.025
  circle w0.05: c0.6,-0.175 r0.025
  circle w0.05: c0.6,-0.325 r0.025
  circle w0.05: c0.45,-0.175 r0.025
  circle w0.05: c-0.6,-0.85 r0.025
  circle w0.05: c-0.45,-0.7 r0.025
  circle w0.05: c-0.45,-0.85 r0.025
  circle w0.05: c-0.6,-0.7 r0.025
  circle w0.05: c-0.075,-0.85 r0.025
  circle w0.05: c0.075,-0.7 r0.025
  circle w0.05: c0.075,-0.85 r0.025
  circle w0.05: c-0.075,-0.7 r0.025
  circle w0.05: c0.45,-0.85 r0.025
  circle w0.05: c0.6,-0.7 r0.025
  circle w0.05: c0.6,-0.85 r0.025
  circle w0.05: c0.45,-0.7 r0.025
  region: -0.6,0.85 -0.6,0.7 -0.45,0.7 -0.45,0.85
  region: -0.6,0.7 -0.6,0.85 -0.65,0.85 -0.65,0.7
  rectangle: -0.6,0.85 -0.45,0.9
  region: -0.45,0.85 -0.45,0.7 -0.4,0.7 -0.4,0.85
  region: -0.45,0.7 -0.6,0.7 -0.6,0.65 -0.45,0.65
  region: -0.075,0.85 -0.075,0.7 0.075,0.7 0.075,0.85
  region: -0.075,0.7 -0.075,0.85 -0.125,0.85 -0.125,0.7
  rectangle: -0.075,0.85 0.075,0.9
  region: 0.075,0.85 0.075,0.7 0.125,0.7 0.125,0.85
  region: 0.075,0.7 -0.075,0.7 -0.075,0.65 0.075,0.65
  region: 0.45,0.85 0.45,0.7 0.6,0.7 0.6,0.85
  region: 0.45,0.7 0.45,0.85 0.4,0.85 0.4,0.7
  rectangle: 0.45,0.85 0.6,0.9
  region: 0.6,0.85 0.6,0.7 0.65,0.7 0.65,0.85
  region: 0.6,0.7 0.45,0.7 0.45,0.65 0.6,0.65
  region: -0.6,0.325 -0.6,0.175 -0.45,0.175 -0.45,0.325
  region: -0.6,0.175 -0.6,0.325 -0.65,0.325 -0.65,0.175
  rectangle: -0.6,0.325 -0.45,0.375
  region: -0.45,0.325 -0.45,0.175 -0.4,0.175 -0.4,0.325
  region: -0.45,0.175 -0.6,0.175 -0.6,0.125 -0.45,0.125
  region: -0.075,0.325 -0.075,0.175 0.075,0.175 0.075,0.325
  region: -0.075,0.175 -0.075,0.325 -0.125,0.325 -0.125,0.175
  rectangle: -0.075,0.325 0.075,0.375
  region: 0.075,0.325 0.075,0.175 0.125,0.175 0.125,0.325
  region: 0.075,0.175 -0.075,0.175 -0.075,0.125 0.075,0.125
  region: 0.45,0.325 0.45,0.175 0.6,0.175 0.6,0.325
  region: 0.45,0.175 0.45,0.325 0.4,0.325 0.4,0.175
  rectangle: 0.45,0.325 0.6,0.375
  region: 0.6,0.325 0.6,0.175 0.65,0.175 0.65,0.325
  region: 0.6,0.175 0.45,0.175 0.45,0.125 0.6,0.125
  region: -0.6,-0.175 -0.6,-0.325 -0.45,-0.325 -0.45,-0.175
  region: -0.6,-0.325 -0.6,-0.175 -0.65,-0.175 -0.65,-0.325
  rectangle: -0.6,-0.175 -0.45,-0.125
  region: -0.45,-0.175 -0.45,-0.325 -0.4,-0.325 -0.4,-0.175
  region: -0.45,-0.325 -0.6,-0.325 -0.6,-0.375 -0.45,-0.375
  region: -0.075,-0.175 -0.075,-0.325 0.075,-0.325 0.075,-0.175
  region: -0.075,-0.325 -0.075,-0.175 -0.125,-0.175 -0.125,-0.325
  rectangle: -0.075,-0.175 0.075,-0.125
  region: 0.075,-0.175 0.075,-0.325 0.125,-0.325 0.125,-0.175
  region: 0.075,-0.325 -0.075,-0.325 -0.075,-0.375 0.075,-0.375
  region: 0.45,-0.175 0.45,-0.325 0.6,-0.325 0.6,-0.175
  region: 0.45,-0.325 0.45,-0.175 0.4,-0.175 0.4,-0.325
  rectangle: 0.45,-0.175 0.6,-0.125
  region: 0.6,-0.175 0.6,-0.325 0.65,-0.325 0.65,-0.175
  region: 0.6,-0.325 0.45,-0.325 0.45,-0.375 0.6,-0.375
  region: -0.6,-0.7 -0.6,-0.85 -0.45,-0.85 -0.45,-0.7
  region: -0.6,-0.85 -0.6,-0.7 -0.65,-0.7 -0.65,-0.85
  rectangle: -0.6,-0.7 -0.45,-0.65
  region: -0.45,-0.7 -0.45,-0.85 -0.4,-0.85 -0.4,-0.7
  region: -0.45,-0.85 -0.6,-0.85 -0.6,-0.9 -0.45,-0.9
  region: -0.075,-0.7 -0.075,-0.85 0.075,-0.85 0.075,-0.7
  region: -0.075,-0.85 -0.075,-0.7 -0.125,-0.7 -0.125,-0.85
  rectangle: -0.075,-0.7 0.075,-0.65
  region: 0.075,-0.7 0.075,-0.85 0.125,-0.85 0.125,-0.7
  region: 0.075,-0.85 -0.075,-0.85 -0.075,-0.9 0.075,-0.9
  region: 0.45,-0.7 0.45,-0.85 0.6,-0.85 0.6,-0.7
  region: 0.45,-0.85 0.45,-0.7 0.4,-0.7 0.4,-0.85
  rectangle: 0.45,-0.7 0.6,-0.65
  region: 0.6,-0.7 0.6,-0.85 0.65,-0.85 0.65,-0.7
  region: 0.6,-0.85 0.45,-0.85 0.45,-0.9 0.6,-0.9
Mechanical 13:
  lines w0.1: -0.845,-1.215 -0.845,1.215 0.845,1.215 0.845,-1.215 -0.845,-1.215
Mechanical 15:
  lines w0.1: -0.5,0 0.5,0 ; 0,-0.5 0,0.5 ; -0.945,-1.315 -0.945,1.315 0.945,1.315 0.945,-1.315 -0.945,-1.315
3D body: height 0.68, standoff 0, extent -0.845,-1.215 0.845,1.215

## SMD50P3X4-1.77X2.07-12V [mm] "Micro SMD, 12-Leads, Body 2.07x1.77mm, Pitch 0.5mm, NSC Recommended"
height 0.68
pads (12):
  round 0.265 smd paste-0.132 mask+0.05: A1(-0.5,0.75) A2(0,0.75) A3(0.5,0.75) B1(-0.5,0.25) B2(0,0.25) B3(0.5,0.25) C1(-0.5,-0.25) C2(0,-0.25) C3(0.5,-0.25) D1(-0.5,-0.75) D2(0,-0.75) D3(0.5,-0.75)
Top Overlay:
  circle w0.1: c-0.99,1.14 r0.05
Top Paste:
  circle w0.05: c-0.6,0.7 r0.025
  circle w0.05: c-0.45,0.85 r0.025
  circle w0.05: c-0.45,0.7 r0.025
  circle w0.05: c-0.6,0.85 r0.025
  circle w0.05: c-0.075,0.7 r0.025
  circle w0.05: c0.075,0.85 r0.025
  circle w0.05: c0.075,0.7 r0.025
  circle w0.05: c-0.075,0.85 r0.025
  circle w0.05: c0.45,0.7 r0.025
  circle w0.05: c0.6,0.85 r0.025
  circle w0.05: c0.6,0.7 r0.025
  circle w0.05: c0.45,0.85 r0.025
  circle w0.05: c-0.6,0.175 r0.025
  circle w0.05: c-0.45,0.325 r0.025
  circle w0.05: c-0.45,0.175 r0.025
  circle w0.05: c-0.6,0.325 r0.025
  circle w0.05: c-0.075,0.175 r0.025
  circle w0.05: c0.075,0.325 r0.025
  circle w0.05: c0.075,0.175 r0.025
  circle w0.05: c-0.075,0.325 r0.025
  circle w0.05: c0.45,0.175 r0.025
  circle w0.05: c0.6,0.325 r0.025
  circle w0.05: c0.6,0.175 r0.025
  circle w0.05: c0.45,0.325 r0.025
  circle w0.05: c-0.6,-0.325 r0.025
  circle w0.05: c-0.45,-0.175 r0.025
  circle w0.05: c-0.45,-0.325 r0.025
  circle w0.05: c-0.6,-0.175 r0.025
  circle w0.05: c-0.075,-0.325 r0.025
  circle w0.05: c0.075,-0.175 r0.025
  circle w0.05: c0.075,-0.325 r0.025
  circle w0.05: c-0.075,-0.175 r0.025
  circle w0.05: c0.45,-0.325 r0.025
  circle w0.05: c0.6,-0.175 r0.025
  circle w0.05: c0.6,-0.325 r0.025
  circle w0.05: c0.45,-0.175 r0.025
  circle w0.05: c-0.6,-0.85 r0.025
  circle w0.05: c-0.45,-0.7 r0.025
  circle w0.05: c-0.45,-0.85 r0.025
  circle w0.05: c-0.6,-0.7 r0.025
  circle w0.05: c-0.075,-0.85 r0.025
  circle w0.05: c0.075,-0.7 r0.025
  circle w0.05: c0.075,-0.85 r0.025
  circle w0.05: c-0.075,-0.7 r0.025
  circle w0.05: c0.45,-0.85 r0.025
  circle w0.05: c0.6,-0.7 r0.025
  circle w0.05: c0.6,-0.85 r0.025
  circle w0.05: c0.45,-0.7 r0.025
  region: -0.6,0.85 -0.6,0.7 -0.45,0.7 -0.45,0.85
  region: -0.6,0.7 -0.6,0.85 -0.65,0.85 -0.65,0.7
  rectangle: -0.6,0.85 -0.45,0.9
  region: -0.45,0.85 -0.45,0.7 -0.4,0.7 -0.4,0.85
  region: -0.45,0.7 -0.6,0.7 -0.6,0.65 -0.45,0.65
  region: -0.075,0.85 -0.075,0.7 0.075,0.7 0.075,0.85
  region: -0.075,0.7 -0.075,0.85 -0.125,0.85 -0.125,0.7
  rectangle: -0.075,0.85 0.075,0.9
  region: 0.075,0.85 0.075,0.7 0.125,0.7 0.125,0.85
  region: 0.075,0.7 -0.075,0.7 -0.075,0.65 0.075,0.65
  region: 0.45,0.85 0.45,0.7 0.6,0.7 0.6,0.85
  region: 0.45,0.7 0.45,0.85 0.4,0.85 0.4,0.7
  rectangle: 0.45,0.85 0.6,0.9
  region: 0.6,0.85 0.6,0.7 0.65,0.7 0.65,0.85
  region: 0.6,0.7 0.45,0.7 0.45,0.65 0.6,0.65
  region: -0.6,0.325 -0.6,0.175 -0.45,0.175 -0.45,0.325
  region: -0.6,0.175 -0.6,0.325 -0.65,0.325 -0.65,0.175
  rectangle: -0.6,0.325 -0.45,0.375
  region: -0.45,0.325 -0.45,0.175 -0.4,0.175 -0.4,0.325
  region: -0.45,0.175 -0.6,0.175 -0.6,0.125 -0.45,0.125
  region: -0.075,0.325 -0.075,0.175 0.075,0.175 0.075,0.325
  region: -0.075,0.175 -0.075,0.325 -0.125,0.325 -0.125,0.175
  rectangle: -0.075,0.325 0.075,0.375
  region: 0.075,0.325 0.075,0.175 0.125,0.175 0.125,0.325
  region: 0.075,0.175 -0.075,0.175 -0.075,0.125 0.075,0.125
  region: 0.45,0.325 0.45,0.175 0.6,0.175 0.6,0.325
  region: 0.45,0.175 0.45,0.325 0.4,0.325 0.4,0.175
  rectangle: 0.45,0.325 0.6,0.375
  region: 0.6,0.325 0.6,0.175 0.65,0.175 0.65,0.325
  region: 0.6,0.175 0.45,0.175 0.45,0.125 0.6,0.125
  region: -0.6,-0.175 -0.6,-0.325 -0.45,-0.325 -0.45,-0.175
  region: -0.6,-0.325 -0.6,-0.175 -0.65,-0.175 -0.65,-0.325
  rectangle: -0.6,-0.175 -0.45,-0.125
  region: -0.45,-0.175 -0.45,-0.325 -0.4,-0.325 -0.4,-0.175
  region: -0.45,-0.325 -0.6,-0.325 -0.6,-0.375 -0.45,-0.375
  region: -0.075,-0.175 -0.075,-0.325 0.075,-0.325 0.075,-0.175
  region: -0.075,-0.325 -0.075,-0.175 -0.125,-0.175 -0.125,-0.325
  rectangle: -0.075,-0.175 0.075,-0.125
  region: 0.075,-0.175 0.075,-0.325 0.125,-0.325 0.125,-0.175
  region: 0.075,-0.325 -0.075,-0.325 -0.075,-0.375 0.075,-0.375
  region: 0.45,-0.175 0.45,-0.325 0.6,-0.325 0.6,-0.175
  region: 0.45,-0.325 0.45,-0.175 0.4,-0.175 0.4,-0.325
  rectangle: 0.45,-0.175 0.6,-0.125
  region: 0.6,-0.175 0.6,-0.325 0.65,-0.325 0.65,-0.175
  region: 0.6,-0.325 0.45,-0.325 0.45,-0.375 0.6,-0.375
  region: -0.6,-0.7 -0.6,-0.85 -0.45,-0.85 -0.45,-0.7
  region: -0.6,-0.85 -0.6,-0.7 -0.65,-0.7 -0.65,-0.85
  rectangle: -0.6,-0.7 -0.45,-0.65
  region: -0.45,-0.7 -0.45,-0.85 -0.4,-0.85 -0.4,-0.7
  region: -0.45,-0.85 -0.6,-0.85 -0.6,-0.9 -0.45,-0.9
  region: -0.075,-0.7 -0.075,-0.85 0.075,-0.85 0.075,-0.7
  region: -0.075,-0.85 -0.075,-0.7 -0.125,-0.7 -0.125,-0.85
  rectangle: -0.075,-0.7 0.075,-0.65
  region: 0.075,-0.7 0.075,-0.85 0.125,-0.85 0.125,-0.7
  region: 0.075,-0.85 -0.075,-0.85 -0.075,-0.9 0.075,-0.9
  region: 0.45,-0.7 0.45,-0.85 0.6,-0.85 0.6,-0.7
  region: 0.45,-0.85 0.45,-0.7 0.4,-0.7 0.4,-0.85
  rectangle: 0.45,-0.7 0.6,-0.65
  region: 0.6,-0.7 0.6,-0.85 0.65,-0.85 0.65,-0.7
  region: 0.6,-0.85 0.45,-0.85 0.45,-0.9 0.6,-0.9
Mechanical 13:
  lines w0.1: -0.885,-1.035 -0.885,1.035 0.885,1.035 0.885,-1.035 -0.885,-1.035
Mechanical 15:
  lines w0.1: -0.5,0 0.5,0 ; 0,-0.5 0,0.5 ; -0.985,-1.135 -0.985,1.135 0.985,1.135 0.985,-1.135 -0.985,-1.135
3D body: height 0.68, standoff 0, extent -0.885,-1.04 0.885,1.04

## SMD50P3X4-1.82X2.17-10V [mm] "Micro SMD, 10-Leads, Body 2.17x1.82mm, Pitch 0.5mm, NSC Recommended"
height 0.68
pads (10):
  round 0.265 smd paste-0.132 mask+0.05: A1(-0.5,0.75) A2(0,0.75) A3(0.5,0.75) B1(-0.5,0.25) B3(0.5,0.25) C1(-0.5,-0.25) C3(0.5,-0.25) D1(-0.5,-0.75) D2(0,-0.75) D3(0.5,-0.75)
Top Overlay:
  circle w0.1: c-1.015,1.19 r0.05
Top Paste:
  circle w0.05: c0.45,-0.7 r0.025
  circle w0.05: c0.6,-0.85 r0.025
  circle w0.05: c0.6,-0.7 r0.025
  circle w0.05: c0.45,-0.85 r0.025
  circle w0.05: c-0.075,-0.7 r0.025
  circle w0.05: c0.075,-0.85 r0.025
  circle w0.05: c0.075,-0.7 r0.025
  circle w0.05: c-0.075,-0.85 r0.025
  circle w0.05: c-0.6,-0.7 r0.025
  circle w0.05: c-0.45,-0.85 r0.025
  circle w0.05: c-0.45,-0.7 r0.025
  circle w0.05: c-0.6,-0.85 r0.025
  circle w0.05: c0.45,-0.175 r0.025
  circle w0.05: c0.6,-0.325 r0.025
  circle w0.05: c0.6,-0.175 r0.025
  circle w0.05: c0.45,-0.325 r0.025
  circle w0.05: c-0.6,-0.175 r0.025
  circle w0.05: c-0.45,-0.325 r0.025
  circle w0.05: c-0.45,-0.175 r0.025
  circle w0.05: c-0.6,-0.325 r0.025
  circle w0.05: c0.45,0.325 r0.025
  circle w0.05: c0.6,0.175 r0.025
  circle w0.05: c0.6,0.325 r0.025
  circle w0.05: c0.45,0.175 r0.025
  circle w0.05: c-0.6,0.325 r0.025
  circle w0.05: c-0.45,0.175 r0.025
  circle w0.05: c-0.45,0.325 r0.025
  circle w0.05: c-0.6,0.175 r0.025
  circle w0.05: c0.45,0.85 r0.025
  circle w0.05: c0.6,0.7 r0.025
  circle w0.05: c0.6,0.85 r0.025
  circle w0.05: c0.45,0.7 r0.025
  circle w0.05: c-0.075,0.85 r0.025
  circle w0.05: c0.075,0.7 r0.025
  circle w0.05: c0.075,0.85 r0.025
  circle w0.05: c-0.075,0.7 r0.025
  circle w0.05: c-0.6,0.85 r0.025
  circle w0.05: c-0.45,0.7 r0.025
  circle w0.05: c-0.45,0.85 r0.025
  circle w0.05: c-0.6,0.7 r0.025
  region: 0.6,-0.85 0.45,-0.85 0.45,-0.9 0.6,-0.9
  region: 0.6,-0.7 0.6,-0.85 0.65,-0.85 0.65,-0.7
  rectangle: 0.45,-0.7 0.6,-0.65
  region: 0.45,-0.85 0.45,-0.7 0.4,-0.7 0.4,-0.85
  region: 0.45,-0.7 0.45,-0.85 0.6,-0.85 0.6,-0.7
  region: 0.075,-0.85 -0.075,-0.85 -0.075,-0.9 0.075,-0.9
  region: 0.075,-0.7 0.075,-0.85 0.125,-0.85 0.125,-0.7
  rectangle: -0.075,-0.7 0.075,-0.65
  region: -0.075,-0.85 -0.075,-0.7 -0.125,-0.7 -0.125,-0.85
  region: -0.075,-0.7 -0.075,-0.85 0.075,-0.85 0.075,-0.7
  region: -0.45,-0.85 -0.6,-0.85 -0.6,-0.9 -0.45,-0.9
  region: -0.45,-0.7 -0.45,-0.85 -0.4,-0.85 -0.4,-0.7
  rectangle: -0.6,-0.7 -0.45,-0.65
  region: -0.6,-0.85 -0.6,-0.7 -0.65,-0.7 -0.65,-0.85
  region: -0.6,-0.7 -0.6,-0.85 -0.45,-0.85 -0.45,-0.7
  region: 0.6,-0.325 0.45,-0.325 0.45,-0.375 0.6,-0.375
  region: 0.6,-0.175 0.6,-0.325 0.65,-0.325 0.65,-0.175
  rectangle: 0.45,-0.175 0.6,-0.125
  region: 0.45,-0.325 0.45,-0.175 0.4,-0.175 0.4,-0.325
  region: 0.45,-0.175 0.45,-0.325 0.6,-0.325 0.6,-0.175
  region: -0.45,-0.325 -0.6,-0.325 -0.6,-0.375 -0.45,-0.375
  region: -0.45,-0.175 -0.45,-0.325 -0.4,-0.325 -0.4,-0.175
  rectangle: -0.6,-0.175 -0.45,-0.125
  region: -0.6,-0.325 -0.6,-0.175 -0.65,-0.175 -0.65,-0.325
  region: -0.6,-0.175 -0.6,-0.325 -0.45,-0.325 -0.45,-0.175
  region: 0.6,0.175 0.45,0.175 0.45,0.125 0.6,0.125
  region: 0.6,0.325 0.6,0.175 0.65,0.175 0.65,0.325
  rectangle: 0.45,0.325 0.6,0.375
  region: 0.45,0.175 0.45,0.325 0.4,0.325 0.4,0.175
  region: 0.45,0.325 0.45,0.175 0.6,0.175 0.6,0.325
  region: -0.45,0.175 -0.6,0.175 -0.6,0.125 -0.45,0.125
  region: -0.45,0.325 -0.45,0.175 -0.4,0.175 -0.4,0.325
  rectangle: -0.6,0.325 -0.45,0.375
  region: -0.6,0.175 -0.6,0.325 -0.65,0.325 -0.65,0.175
  region: -0.6,0.325 -0.6,0.175 -0.45,0.175 -0.45,0.325
  region: 0.6,0.7 0.45,0.7 0.45,0.65 0.6,0.65
  region: 0.6,0.85 0.6,0.7 0.65,0.7 0.65,0.85
  rectangle: 0.45,0.85 0.6,0.9
  region: 0.45,0.7 0.45,0.85 0.4,0.85 0.4,0.7
  region: 0.45,0.85 0.45,0.7 0.6,0.7 0.6,0.85
  region: 0.075,0.7 -0.075,0.7 -0.075,0.65 0.075,0.65
  region: 0.075,0.85 0.075,0.7 0.125,0.7 0.125,0.85
  rectangle: -0.075,0.85 0.075,0.9
  region: -0.075,0.7 -0.075,0.85 -0.125,0.85 -0.125,0.7
  region: -0.075,0.85 -0.075,0.7 0.075,0.7 0.075,0.85
  region: -0.45,0.7 -0.6,0.7 -0.6,0.65 -0.45,0.65
  region: -0.45,0.85 -0.45,0.7 -0.4,0.7 -0.4,0.85
  rectangle: -0.6,0.85 -0.45,0.9
  region: -0.6,0.7 -0.6,0.85 -0.65,0.85 -0.65,0.7
  region: -0.6,0.85 -0.6,0.7 -0.45,0.7 -0.45,0.85
Mechanical 13:
  lines w0.1: -0.91,-1.085 0.91,-1.085 0.91,1.085 -0.91,1.085 -0.91,-1.085
Mechanical 15:
  lines w0.1: -0.5,0 0.5,0 ; 0,-0.5 0,0.5 ; -1.01,-1.185 1.01,-1.185 1.01,1.185 -1.01,1.185 -1.01,-1.185
3D body: height 0.68, standoff 0, extent -0.91,-1.09 0.91,1.09

## SMD50P3X4-1.97X2.3-12V [mm] "Micro SMD, 12-Leads, Body 2.3x1.97mm, Pitch 0.5mm, NSC Recommended"
height 0.68
pads (12):
  round 0.265 smd paste-0.132 mask+0.05: A1(-0.5,0.75) A2(0,0.75) A3(0.5,0.75) B1(-0.5,0.25) B2(0,0.25) B3(0.5,0.25) C1(-0.5,-0.25) C2(0,-0.25) C3(0.5,-0.25) D1(-0.5,-0.75) D2(0,-0.75) D3(0.5,-0.75)
Top Overlay:
  circle w0.1: c-1.09,1.255 r0.05
Top Paste:
  circle w0.05: c-0.6,0.7 r0.025
  circle w0.05: c-0.45,0.85 r0.025
  circle w0.05: c-0.45,0.7 r0.025
  circle w0.05: c-0.6,0.85 r0.025
  circle w0.05: c-0.075,0.7 r0.025
  circle w0.05: c0.075,0.85 r0.025
  circle w0.05: c0.075,0.7 r0.025
  circle w0.05: c-0.075,0.85 r0.025
  circle w0.05: c0.45,0.7 r0.025
  circle w0.05: c0.6,0.85 r0.025
  circle w0.05: c0.6,0.7 r0.025
  circle w0.05: c0.45,0.85 r0.025
  circle w0.05: c-0.6,0.175 r0.025
  circle w0.05: c-0.45,0.325 r0.025
  circle w0.05: c-0.45,0.175 r0.025
  circle w0.05: c-0.6,0.325 r0.025
  circle w0.05: c-0.075,0.175 r0.025
  circle w0.05: c0.075,0.325 r0.025
  circle w0.05: c0.075,0.175 r0.025
  circle w0.05: c-0.075,0.325 r0.025
  circle w0.05: c0.45,0.175 r0.025
  circle w0.05: c0.6,0.325 r0.025
  circle w0.05: c0.6,0.175 r0.025
  circle w0.05: c0.45,0.325 r0.025
  circle w0.05: c-0.6,-0.325 r0.025
  circle w0.05: c-0.45,-0.175 r0.025
  circle w0.05: c-0.45,-0.325 r0.025
  circle w0.05: c-0.6,-0.175 r0.025
  circle w0.05: c-0.075,-0.325 r0.025
  circle w0.05: c0.075,-0.175 r0.025
  circle w0.05: c0.075,-0.325 r0.025
  circle w0.05: c-0.075,-0.175 r0.025
  circle w0.05: c0.45,-0.325 r0.025
  circle w0.05: c0.6,-0.175 r0.025
  circle w0.05: c0.6,-0.325 r0.025
  circle w0.05: c0.45,-0.175 r0.025
  circle w0.05: c-0.6,-0.85 r0.025
  circle w0.05: c-0.45,-0.7 r0.025
  circle w0.05: c-0.45,-0.85 r0.025
  circle w0.05: c-0.6,-0.7 r0.025
  circle w0.05: c-0.075,-0.85 r0.025
  circle w0.05: c0.075,-0.7 r0.025
  circle w0.05: c0.075,-0.85 r0.025
  circle w0.05: c-0.075,-0.7 r0.025
  circle w0.05: c0.45,-0.85 r0.025
  circle w0.05: c0.6,-0.7 r0.025
  circle w0.05: c0.6,-0.85 r0.025
  circle w0.05: c0.45,-0.7 r0.025
  region: -0.6,0.85 -0.6,0.7 -0.45,0.7 -0.45,0.85
  region: -0.6,0.7 -0.6,0.85 -0.65,0.85 -0.65,0.7
  rectangle: -0.6,0.85 -0.45,0.9
  region: -0.45,0.85 -0.45,0.7 -0.4,0.7 -0.4,0.85
  region: -0.45,0.7 -0.6,0.7 -0.6,0.65 -0.45,0.65
  region: -0.075,0.85 -0.075,0.7 0.075,0.7 0.075,0.85
  region: -0.075,0.7 -0.075,0.85 -0.125,0.85 -0.125,0.7
  rectangle: -0.075,0.85 0.075,0.9
  region: 0.075,0.85 0.075,0.7 0.125,0.7 0.125,0.85
  region: 0.075,0.7 -0.075,0.7 -0.075,0.65 0.075,0.65
  region: 0.45,0.85 0.45,0.7 0.6,0.7 0.6,0.85
  region: 0.45,0.7 0.45,0.85 0.4,0.85 0.4,0.7
  rectangle: 0.45,0.85 0.6,0.9
  region: 0.6,0.85 0.6,0.7 0.65,0.7 0.65,0.85
  region: 0.6,0.7 0.45,0.7 0.45,0.65 0.6,0.65
  region: -0.6,0.325 -0.6,0.175 -0.45,0.175 -0.45,0.325
  region: -0.6,0.175 -0.6,0.325 -0.65,0.325 -0.65,0.175
  rectangle: -0.6,0.325 -0.45,0.375
  region: -0.45,0.325 -0.45,0.175 -0.4,0.175 -0.4,0.325
  region: -0.45,0.175 -0.6,0.175 -0.6,0.125 -0.45,0.125
  region: -0.075,0.325 -0.075,0.175 0.075,0.175 0.075,0.325
  region: -0.075,0.175 -0.075,0.325 -0.125,0.325 -0.125,0.175
  rectangle: -0.075,0.325 0.075,0.375
  region: 0.075,0.325 0.075,0.175 0.125,0.175 0.125,0.325
  region: 0.075,0.175 -0.075,0.175 -0.075,0.125 0.075,0.125
  region: 0.45,0.325 0.45,0.175 0.6,0.175 0.6,0.325
  region: 0.45,0.175 0.45,0.325 0.4,0.325 0.4,0.175
  rectangle: 0.45,0.325 0.6,0.375
  region: 0.6,0.325 0.6,0.175 0.65,0.175 0.65,0.325
  region: 0.6,0.175 0.45,0.175 0.45,0.125 0.6,0.125
  region: -0.6,-0.175 -0.6,-0.325 -0.45,-0.325 -0.45,-0.175
  region: -0.6,-0.325 -0.6,-0.175 -0.65,-0.175 -0.65,-0.325
  rectangle: -0.6,-0.175 -0.45,-0.125
  region: -0.45,-0.175 -0.45,-0.325 -0.4,-0.325 -0.4,-0.175
  region: -0.45,-0.325 -0.6,-0.325 -0.6,-0.375 -0.45,-0.375
  region: -0.075,-0.175 -0.075,-0.325 0.075,-0.325 0.075,-0.175
  region: -0.075,-0.325 -0.075,-0.175 -0.125,-0.175 -0.125,-0.325
  rectangle: -0.075,-0.175 0.075,-0.125
  region: 0.075,-0.175 0.075,-0.325 0.125,-0.325 0.125,-0.175
  region: 0.075,-0.325 -0.075,-0.325 -0.075,-0.375 0.075,-0.375
  region: 0.45,-0.175 0.45,-0.325 0.6,-0.325 0.6,-0.175
  region: 0.45,-0.325 0.45,-0.175 0.4,-0.175 0.4,-0.325
  rectangle: 0.45,-0.175 0.6,-0.125
  region: 0.6,-0.175 0.6,-0.325 0.65,-0.325 0.65,-0.175
  region: 0.6,-0.325 0.45,-0.325 0.45,-0.375 0.6,-0.375
  region: -0.6,-0.7 -0.6,-0.85 -0.45,-0.85 -0.45,-0.7
  region: -0.6,-0.85 -0.6,-0.7 -0.65,-0.7 -0.65,-0.85
  rectangle: -0.6,-0.7 -0.45,-0.65
  region: -0.45,-0.7 -0.45,-0.85 -0.4,-0.85 -0.4,-0.7
  region: -0.45,-0.85 -0.6,-0.85 -0.6,-0.9 -0.45,-0.9
  region: -0.075,-0.7 -0.075,-0.85 0.075,-0.85 0.075,-0.7
  region: -0.075,-0.85 -0.075,-0.7 -0.125,-0.7 -0.125,-0.85
  rectangle: -0.075,-0.7 0.075,-0.65
  region: 0.075,-0.7 0.075,-0.85 0.125,-0.85 0.125,-0.7
  region: 0.075,-0.85 -0.075,-0.85 -0.075,-0.9 0.075,-0.9
  region: 0.45,-0.7 0.45,-0.85 0.6,-0.85 0.6,-0.7
  region: 0.45,-0.85 0.45,-0.7 0.4,-0.7 0.4,-0.85
  rectangle: 0.45,-0.7 0.6,-0.65
  region: 0.6,-0.7 0.6,-0.85 0.65,-0.85 0.65,-0.7
  region: 0.6,-0.85 0.45,-0.85 0.45,-0.9 0.6,-0.9
Mechanical 13:
  lines w0.1: -0.985,-1.15 -0.985,1.15 0.985,1.15 0.985,-1.15 -0.985,-1.15
Mechanical 15:
  lines w0.1: -0.5,0 0.5,0 ; 0,-0.5 0,0.5 ; -1.085,-1.25 -1.085,1.25 1.085,1.25 1.085,-1.25 -1.085,-1.25
3D body: height 0.68, standoff 0, extent -0.985,-1.15 0.985,1.15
